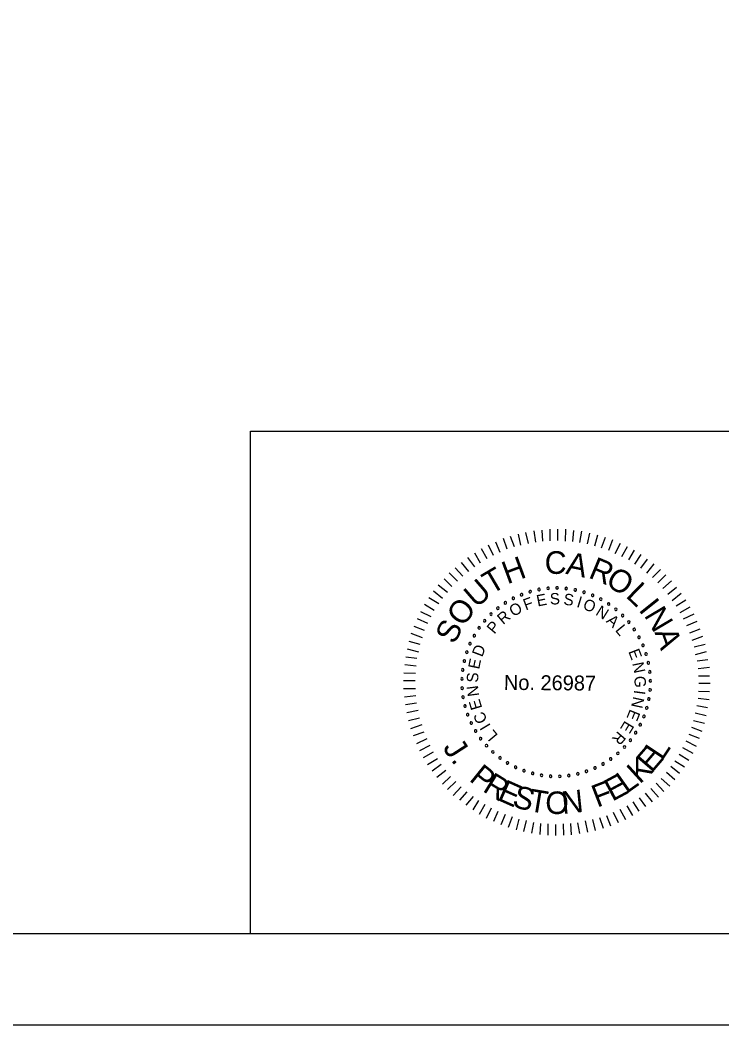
# Model space of a CAD drawing. Extents: x -121.2 to -24.9, y 6.4 to 65.
# Drawn here: x -64.16 to -53.92, y 6.35 to 21.02 of the extents above; entities that cross this region are included whole.
import ezdxf

# ---------------------------------------------------------------- set-up
doc = ezdxf.new("R2010")
doc.units = 0
for name, color, linetype in [('BR_BORDER LINES', 7, 'Continuous'), ('BR_TEXT', 7, 'Continuous'), ('Level 31', 7, 'Continuous')]:
    doc.layers.add(name, color=color, linetype=linetype)

msp = doc.modelspace()

# ---------------------------------------------------------------- linework, layer by layer
at = {"layer": 'BR_BORDER LINES'}
for p, q in [((-60.804, 15.017), (-46.496, 15.017)), ((-60.804, 7.683), (-60.804, 15.017)), ((-116.272, 7.683), (-26.496, 7.683))]:
    msp.add_line(p, q, dxfattribs=at)
at = {"layer": 'BR_TEXT'}
for p, q in [((-56.855, 13.352), (-56.89, 13.515)), ((-56.744, 13.379), (-56.782, 13.537)), ((-56.639, 13.398), (-56.663, 13.561)), ((-56.534, 13.409), (-56.544, 13.572)), ((-56.428, 13.415), (-56.427, 13.587)), ((-56.316, 13.421), (-56.315, 13.586)), ((-56.204, 13.413), (-56.198, 13.585)), ((-56.097, 13.405), (-56.084, 13.568)), ((-55.994, 13.393), (-55.965, 13.555)), ((-55.886, 13.372), (-55.848, 13.529)), ((-55.777, 13.343), (-55.734, 13.505)), ((-57.258, 13.202), (-57.328, 13.352)), ((-57.16, 13.247), (-57.223, 13.396)), ((-57.056, 13.292), (-57.112, 13.448)), ((-56.951, 13.326), (-57.009, 13.479)), ((-55.679, 13.315), (-55.62, 13.468)), ((-55.574, 13.28), (-55.515, 13.435)), ((-55.478, 13.233), (-55.403, 13.381)), ((-57.445, 13.092), (-57.526, 13.236)), ((-57.35, 13.155), (-57.432, 13.3)), ((-55.382, 13.187), (-55.298, 13.335)), ((-55.282, 13.138), (-55.196, 13.281)), ((-55.193, 13.073), (-55.103, 13.216)), ((-57.617, 12.967), (-57.724, 13.101)), ((-57.528, 13.035), (-57.632, 13.171)), ((-55.104, 13.015), (-55.007, 13.149)), ((-55.018, 12.946), (-54.909, 13.078)), ((-57.783, 12.829), (-57.901, 12.947)), ((-57.705, 12.902), (-57.816, 13.021)), ((-54.934, 12.879), (-54.818, 12.997)), ((-54.859, 12.805), (-54.743, 12.921)), ((-57.929, 12.663), (-58.061, 12.767)), ((-57.862, 12.747), (-57.978, 12.86)), ((-54.784, 12.722), (-54.657, 12.833)), ((-57.998, 12.574), (-58.13, 12.681)), ((-54.712, 12.636), (-54.587, 12.738)), ((-54.648, 12.547), (-54.517, 12.651)), ((-58.121, 12.399), (-58.264, 12.485)), ((-58.056, 12.497), (-58.2, 12.585)), ((-54.589, 12.468), (-54.449, 12.554)), ((-58.168, 12.308), (-58.318, 12.382)), ((-54.531, 12.37), (-54.388, 12.453)), ((-54.483, 12.278), (-54.329, 12.35)), ((-58.214, 12.21), (-58.367, 12.278)), ((-54.436, 12.179), (-54.284, 12.244)), ((-58.294, 12), (-58.458, 12.061)), ((-58.261, 12.107), (-58.416, 12.166)), ((-54.391, 12.075), (-54.24, 12.131)), ((-58.327, 11.904), (-58.489, 11.945)), ((-54.355, 11.968), (-54.202, 12.026)), ((-54.329, 11.871), (-54.168, 11.909)), ((-58.346, 11.792), (-58.512, 11.835)), ((-54.307, 11.759), (-54.146, 11.799)), ((-58.386, 11.587), (-58.551, 11.606)), ((-58.374, 11.696), (-58.536, 11.718)), ((-54.285, 11.663), (-54.127, 11.682)), ((-58.394, 11.481), (-58.566, 11.483)), ((-54.267, 11.553), (-54.105, 11.57)), ((-54.264, 11.447), (-54.103, 11.446)), ((-58.4, 11.372), (-58.567, 11.373)), ((-54.258, 11.338), (-54.095, 11.336)), ((-58.396, 11.257), (-58.568, 11.254)), ((-58.39, 11.154), (-58.555, 11.135)), ((-54.266, 11.223), (-54.105, 11.217)), ((-58.379, 11.044), (-58.542, 11.02)), ((-54.29, 11.011), (-54.132, 10.984)), ((-54.271, 11.12), (-54.109, 11.098)), ((-58.353, 10.939), (-58.52, 10.904)), ((-54.314, 10.905), (-54.154, 10.867)), ((-58.335, 10.826), (-58.498, 10.789)), ((-58.304, 10.728), (-58.469, 10.672)), ((-54.338, 10.793), (-54.178, 10.753)), ((-58.273, 10.625), (-58.429, 10.569)), ((-54.403, 10.593), (-54.253, 10.534)), ((-54.366, 10.695), (-54.213, 10.637)), ((-58.228, 10.526), (-58.382, 10.454)), ((-58.183, 10.429), (-58.335, 10.35)), ((-54.45, 10.495), (-54.3, 10.42)), ((-58.138, 10.331), (-58.283, 10.247)), ((-54.548, 10.301), (-54.407, 10.215)), ((-54.499, 10.399), (-54.346, 10.318)), ((-58.075, 10.232), (-58.22, 10.148)), ((-58.018, 10.153), (-58.152, 10.056)), ((-54.668, 10.126), (-54.539, 10.026)), ((-54.608, 10.203), (-54.469, 10.117)), ((-57.95, 10.064), (-58.084, 9.959)), ((-57.885, 9.974), (-58.002, 9.865)), ((-54.733, 10.037), (-54.61, 9.931)), ((-57.808, 9.904), (-57.927, 9.784)), ((-54.883, 9.88), (-54.77, 9.758)), ((-54.807, 9.948), (-54.682, 9.837)), ((-57.73, 9.824), (-57.844, 9.701)), ((-57.644, 9.754), (-57.753, 9.629)), ((-57.555, 9.685), (-57.662, 9.558)), ((-55.044, 9.733), (-54.938, 9.606)), ((-54.959, 9.801), (-54.846, 9.676)), ((-57.473, 9.627), (-57.557, 9.488)), ((-57.38, 9.567), (-57.464, 9.423)), ((-55.311, 9.55), (-55.228, 9.405)), ((-55.222, 9.608), (-55.134, 9.468)), ((-55.132, 9.665), (-55.037, 9.536)), ((-57.289, 9.513), (-57.361, 9.365)), ((-57.191, 9.467), (-57.256, 9.319)), ((-57.088, 9.42), (-57.147, 9.27)), ((-56.983, 9.387), (-57.044, 9.232)), ((-55.606, 9.408), (-55.55, 9.256)), ((-55.509, 9.453), (-55.437, 9.304)), ((-55.413, 9.498), (-55.331, 9.348)), ((-56.888, 9.354), (-56.925, 9.197)), ((-56.778, 9.335), (-56.818, 9.171)), ((-56.673, 9.305), (-56.699, 9.149)), ((-56.568, 9.292), (-56.58, 9.128)), ((-56.462, 9.285), (-56.464, 9.12)), ((-56.35, 9.277), (-56.352, 9.114)), ((-56.238, 9.283), (-56.235, 9.118)), ((-56.131, 9.289), (-56.121, 9.124)), ((-56.028, 9.299), (-56.001, 9.143)), ((-55.92, 9.328), (-55.884, 9.163)), ((-55.81, 9.346), (-55.77, 9.187)), ((-55.711, 9.377), (-55.655, 9.221))]:
    msp.add_line(p, q, dxfattribs=at)
for centre, start, end in [((-56.847, 12.632), 21.6807, 201.6807), ((-56.847, 12.632), 201.6807, 21.6807), ((-56.721, 12.674), 16.1422, 196.1422), ((-56.721, 12.674), 196.1422, 16.1422), ((-56.592, 12.705), 10.6038, 190.6038), ((-56.592, 12.705), 190.6038, 10.6038), ((-56.46, 12.723), 5.0653, 185.0653), ((-56.46, 12.723), 185.0653, 5.0653), ((-56.328, 12.728), 359.5268, 179.5268), ((-56.328, 12.728), 179.5268, 359.5268), ((-56.195, 12.72), 353.9884, 173.9884), ((-56.195, 12.72), 173.9884, 353.9884), ((-56.064, 12.699), 348.4499, 168.4499), ((-56.064, 12.699), 168.4499, 348.4499), ((-55.935, 12.666), 162.9114, 342.9114), ((-55.935, 12.666), 342.9114, 162.9114), ((-55.81, 12.621), 157.373, 337.373), ((-55.81, 12.621), 337.373, 157.373), ((-57.083, 12.511), 32.7576, 212.7576), ((-57.083, 12.511), 212.7576, 32.7576), ((-56.968, 12.577), 27.2191, 207.2191), ((-56.968, 12.577), 207.2191, 27.2191), ((-55.69, 12.564), 151.8345, 331.8345), ((-55.69, 12.564), 331.8345, 151.8345), ((-55.576, 12.495), 146.2961, 326.2961), ((-55.576, 12.495), 326.2961, 146.2961), ((-57.292, 12.347), 43.8345, 223.8345), ((-57.292, 12.347), 223.8345, 43.8345), ((-57.192, 12.434), 38.2961, 218.2961), ((-57.192, 12.434), 218.2961, 38.2961), ((-55.47, 12.416), 140.7576, 320.7576), ((-55.47, 12.416), 320.7576, 140.7576), ((-55.371, 12.327), 135.2191, 315.2191), ((-55.371, 12.327), 315.2191, 135.2191), ((-57.384, 12.25), 49.373, 229.373), ((-57.384, 12.25), 229.373, 49.373), ((-55.282, 12.229), 129.6807, 309.6807), ((-55.282, 12.229), 309.6807, 129.6807), ((-57.537, 12.033), 60.4499, 240.4499), ((-57.537, 12.033), 240.4499, 60.4499), ((-57.465, 12.145), 54.9114, 234.9114), ((-57.465, 12.145), 234.9114, 54.9114), ((-55.202, 12.122), 124.1422, 304.1422), ((-55.202, 12.122), 304.1422, 124.1422), ((-55.133, 12.009), 298.6038, 118.6038), ((-57.597, 11.915), 65.9884, 245.9884), ((-57.597, 11.915), 245.9884, 65.9884), ((-55.133, 12.009), 118.6038, 298.6038), ((-55.075, 11.889), 113.0653, 293.0653), ((-55.075, 11.889), 293.0653, 113.0653), ((-57.645, 11.791), 71.5268, 251.5268), ((-57.645, 11.791), 251.5268, 71.5268), ((-55.029, 11.764), 107.5268, 287.5268), ((-55.029, 11.764), 287.5268, 107.5268), ((-57.681, 11.663), 77.0653, 257.0653), ((-57.681, 11.663), 257.0653, 77.0653), ((-54.996, 11.636), 101.9884, 281.9884), ((-54.996, 11.636), 281.9884, 101.9884), ((-57.705, 11.532), 82.6038, 262.6038), ((-57.705, 11.532), 262.6038, 82.6038), ((-54.975, 11.504), 96.4499, 276.4499), ((-54.975, 11.504), 276.4499, 96.4499), ((-57.716, 11.4), 88.1422, 268.1422), ((-57.716, 11.4), 268.1422, 88.1422), ((-54.967, 11.372), 90.9114, 270.9114), ((-54.967, 11.372), 270.9114, 90.9114), ((-57.714, 11.267), 93.6807, 273.6807), ((-57.7, 11.135), 99.2191, 279.2191), ((-57.714, 11.267), 273.6807, 93.6807), ((-57.7, 11.135), 279.2191, 99.2191), ((-54.971, 11.239), 85.373, 265.373), ((-54.971, 11.239), 265.373, 85.373), ((-57.672, 11.005), 104.7576, 284.7576), ((-57.672, 11.005), 284.7576, 104.7576), ((-54.989, 11.107), 79.8345, 259.8345), ((-54.989, 11.107), 259.8345, 79.8345), ((-57.632, 10.878), 110.2961, 290.2961), ((-57.632, 10.878), 290.2961, 110.2961), ((-55.061, 10.852), 68.7576, 248.7576), ((-55.061, 10.852), 248.7576, 68.7576), ((-55.019, 10.978), 74.2961, 254.2961), ((-55.019, 10.978), 254.2961, 74.2961), ((-57.581, 10.756), 115.8345, 295.8345), ((-57.581, 10.756), 295.8345, 115.8345), ((-55.115, 10.731), 63.2191, 243.2191), ((-55.115, 10.731), 243.2191, 63.2191), ((-57.517, 10.639), 121.373, 301.373), ((-57.517, 10.639), 301.373, 121.373), ((-55.181, 10.615), 57.6807, 237.6807), ((-55.181, 10.615), 237.6807, 57.6807), ((-57.443, 10.529), 126.9114, 306.9114), ((-57.443, 10.529), 306.9114, 126.9114), ((-57.358, 10.426), 132.4499, 312.4499), ((-57.358, 10.426), 312.4499, 132.4499), ((-55.344, 10.406), 46.6038, 226.6038), ((-55.344, 10.406), 226.6038, 46.6038), ((-55.258, 10.507), 52.1422, 232.1422), ((-55.258, 10.507), 232.1422, 52.1422), ((-57.264, 10.333), 137.9884, 317.9884), ((-57.264, 10.333), 317.9884, 137.9884), ((-57.161, 10.248), 323.5268, 143.5268), ((-55.44, 10.314), 41.0653, 221.0653), ((-55.44, 10.314), 221.0653, 41.0653), ((-57.161, 10.248), 143.5268, 323.5268), ((-57.051, 10.174), 149.0653, 329.0653), ((-57.051, 10.174), 329.0653, 149.0653), ((-56.934, 10.112), 334.6038, 154.6038), ((-55.657, 10.16), 29.9884, 209.9884), ((-55.657, 10.16), 209.9884, 29.9884), ((-55.545, 10.232), 35.5268, 215.5268), ((-55.545, 10.232), 215.5268, 35.5268), ((-56.934, 10.112), 154.6038, 334.6038), ((-56.811, 10.06), 160.1422, 340.1422), ((-56.811, 10.06), 340.1422, 160.1422), ((-56.684, 10.021), 345.6807, 165.6807), ((-56.684, 10.021), 165.6807, 345.6807), ((-56.554, 9.994), 351.2191, 171.2191), ((-56.554, 9.994), 171.2191, 351.2191), ((-56.422, 9.98), 356.7576, 176.7576), ((-56.422, 9.98), 176.7576, 356.7576), ((-56.289, 9.978), 2.2961, 182.2961), ((-56.289, 9.978), 182.2961, 2.2961), ((-56.157, 9.99), 7.8345, 187.8345), ((-56.157, 9.99), 187.8345, 7.8345), ((-56.026, 10.014), 13.373, 193.373), ((-56.026, 10.014), 193.373, 13.373), ((-55.899, 10.051), 18.9114, 198.9114), ((-55.899, 10.051), 198.9114, 18.9114), ((-55.775, 10.1), 24.4499, 204.4499), ((-55.775, 10.1), 204.4499, 24.4499)]:
    msp.add_arc(centre, 0.0187, start, end, dxfattribs=at)
at = {"layer": 'Level 31'}
msp.add_lwpolyline([(-121.161, 65.017), (-121.161, 6.35), (-25.161, 6.35), (-25.161, 65.017)], dxfattribs=at)

# ---------------------------------------------------------------- texts
at = {"layer": 'BR_TEXT'}
for s, height, rotation, p in [('C', 0.331, 359.5482, (-56.51, 12.935)), ('A', 0.331, 348.1981, (-56.213, 12.937)), ('H', 0.331, 20.3637, (-57.055, 12.779)), ('R', 0.331, 337.4344, (-55.884, 12.884)), ('T', 0.331, 30.4992, (-57.29, 12.626)), ('O', 0.33, 326.5869, (-55.638, 12.786)), ('U', 0.331, 40.8022, (-57.506, 12.426)), ('L', 0.331, 315.9488, (-55.338, 12.605)), ('E', 0.166, 11.4103, (-56.611, 12.456)), ('S', 0.166, 2.208, (-56.431, 12.485)), ('S', 0.166, 352.6608, (-56.241, 12.485)), ('O', 0.331, 52.0267, (-57.705, 12.149)), ('O', 0.166, 30.8477, (-56.965, 12.302)), ('F', 0.166, 20.6127, (-56.785, 12.398)), ('I', 0.166, 343.1136, (-56.053, 12.453)), ('O', 0.166, 338.4392, (-55.964, 12.426)), ('N', 0.166, 328.2042, (-55.778, 12.342)), ('I', 0.331, 308.6613, (-55.148, 12.407)), ('R', 0.166, 40.3949, (-57.115, 12.185)), ('N', 0.331, 300.7037, (-55.066, 12.329)), ('S', 0.33, 63.2511, (-57.826, 11.894)), ('P', 0.166, 49.9421, (-57.243, 12.045)), ('A', 0.166, 318.657, (-55.621, 12.235)), ('L', 0.166, 309.4546, (-55.488, 12.109)), ('A', 0.331, 289.4792, (-54.908, 12.081)), ('D', 0.166, 69.0364, (-57.421, 11.711)), ('E', 0.166, 291.049, (-55.291, 11.801)), ('E', 0.166, 78.2388, (-57.466, 11.533)), ('N', 0.166, 281.8466, (-55.232, 11.628)), ('S', 0.166, 87.786, (-57.481, 11.344)), ('No. 26987', 0.218, 359.5268, (-57.105, 11.241)), ('N', 0.166, 97.3332, (-57.464, 11.154)), ('G', 0.166, 272.2995, (-55.201, 11.441)), ('I', 0.166, 262.4084, (-55.202, 11.244)), ('E', 0.166, 106.5355, (-57.419, 10.977)), ('N', 0.166, 257.7339, (-55.214, 11.151)), ('C', 0.166, 116.4266, (-57.339, 10.797)), ('E', 0.166, 248.1867, (-55.262, 10.968)), ('I', 0.166, 121.1011, (-57.291, 10.717)), ('E', 0.166, 238.9844, (-55.337, 10.8)), ('L', 0.166, 129.9595, (-57.183, 10.578)), ('R', 0.166, 229.782, (-55.437, 10.647)), ('J', 0.329, 302.9559, (-58.004, 10.395)), ('E', 0.329, 49.3639, (-54.948, 10.017)), ('L', 0.329, 56.4247, (-54.795, 10.198)), ('K', 0.329, 42.3031, (-55.122, 9.857)), ('.', 0.329, 309.3974, (-57.886, 10.214)), ('P', 0.329, 321.1035, (-57.624, 9.923)), ('R', 0.329, 328.5359, (-57.428, 9.768)), ('E', 0.329, 28.1814, (-55.523, 9.606)), ('L', 0.329, 35.2422, (-55.315, 9.719)), ('E', 0.329, 335.9684, (-57.215, 9.64)), ('S', 0.329, 343.0292, (-56.998, 9.545)), ('F', 0.329, 21.1206, (-55.743, 9.519)), ('T', 0.329, 350.4617, (-56.759, 9.474)), ('O', 0.329, 358.1419, (-56.504, 9.434)), ('N', 0.329, 5.8221, (-56.247, 9.428))]:
    msp.add_text(s, height=height, rotation=rotation, dxfattribs=at).set_placement(p)

doc.saveas('drawing.dxf')
